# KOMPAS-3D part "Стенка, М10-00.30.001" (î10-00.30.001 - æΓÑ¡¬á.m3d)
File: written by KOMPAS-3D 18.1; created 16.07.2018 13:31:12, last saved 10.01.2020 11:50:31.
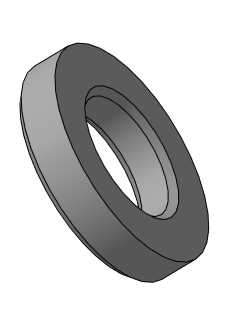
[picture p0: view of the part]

Document properties: Автор: Милов; Полное имя файла: D:\Magna\Магна Ins\Магна ins 10\М10-00.00.000\3Д\М10-00.30.001 - Стенка.m3d

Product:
- Part/product: Стенка  | designation М10-00.30.001
    Материал: Полипропилен  ГОСТ 26996-86 (density 900 kg/m3)
    Масса: 0.226956
    Раздел спецификации: Детали
    Форматы листов документа: A4
    source file: М10-00.30.001 - Стенка.cdw
- Part/product: Стенка ПВХ  | designation М10-00.30.001
    Материал: Полипропилен  ГОСТ 26996-86 (density 900 kg/m3)
    Масса: 0.266182
    Раздел спецификации: Детали
    Форматы листов документа: A4

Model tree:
1. Эскиз:1
2. Операция выдавливания:1
     Расстояние 1 = 27
3. Фаска:1  (with: Операция выдавливания:1)
     Угол = 45; Длина 1 = 4; Длина 2 = 4
4. Фаска:11  (with: Операция выдавливания:1)  (labels: Полипропилен  ГОСТ 26996-86; М10-00.20.000 - Корпус.a3d)
     Угол = 45; Длина 1 = 5; Длина 2 = 5
5. Эскиз:8  (with: Операция выдавливания:1)
6. Элемент выдавливания:3
     Расстояние 2 = 25
7. Эскиз:12  (with: Операция выдавливания:1, Фаска:3)
8. Элемент выдавливания:5
     Расстояние 1 = 20
9. Эскиз:13  (with: Операция выдавливания:1, Элемент выдавливания:2)
10. Элемент выдавливания:6
     Расстояние 2 = 5
11. Элемент выдавливания:7  (with: Элемент выдавливания:5)
     Расстояние 1 = 3.5
12. Фаска:6  (with: Элемент выдавливания:7)
     Угол = 15; Длина 1 = 5; Длина 2 = 1.33975
13. Элемент выдавливания:8  (with: Операция выдавливания:1)
     Расстояние 1 = 36
14. Эскиз:14  (with: Элемент выдавливания:8)
15. Элемент выдавливания:9
     Расстояние 2 = 61
16. Фаска:9  (with: Элемент выдавливания:9)
     Угол = 15; Длина 1 = 5; Длина 2 = 1.33975

Referenced files in D:\Magna\Магна Ins\Магна ins 10\М10-00.00.000\3Д\: М10-00.20.000 - Корпус.a3d
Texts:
  Обечайка ПВХ\Стенка ПВХ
